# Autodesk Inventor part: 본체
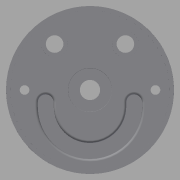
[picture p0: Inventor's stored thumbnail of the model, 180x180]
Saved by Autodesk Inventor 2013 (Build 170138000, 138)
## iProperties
Created: 2015-04
Part Number: 본체
Material: 일반
Document SubType Name: Modeling
Designer: WINDOWS7
Density: 1 g/cm^3
Author: WINDOWS7
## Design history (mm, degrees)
sketch "스케치1"
  geometry: C1 r 95 at (0, 0); 1 further point
  constraints: 1 centre point, 1 coincident
  dimensions: "d0" = 190 diameter of C1
extrude "돌출1" new body sketch "스케치1" distance "d1" = 32; taper "d2" = 0 deg
sketch "스케치2"
  geometry: L1 (0, 0)-(95, 0); L2 (0, 0)-(94.638, -8.28); L3 (0, 0)-(0, -95); L4 (0, 0)-(-94.638, -8.28); A1 r 95 centre (0, 0) between (95, 0) and (0, -95) reference; A2 r 95 centre (0, 0) between (-94.638, -8.28) and (94.638, -8.28)
  constraints: 8 end point, 6 point on circle, 1 centre point, 1 coincident, 1 horizontal, 1 perpendicular, 1 symmetric about line
  dimensions: "d3" = 5 deg angle of L1 L2
extrude "돌출2" cut sketch "스케치2" distance "d4" = 5; taper "d5" = 0 deg
sketch "스케치3"
  geometry: L1 (0, 0)-(-95, 0); L2 (0, 0)-(-50.912, 50.912); L3 (0, 0)-(0, 95); L4 (0, 0)-(50.912, 50.912); L5 (36.062, 36.062)-(50.912, 50.912); L6 (-36.062, 36.062)-(-50.912, 50.912); A1 r 95 centre (0, 0) between (-95, 0) and (0, 95) reference; A2 r 51 centre (0, 0) between (36.062, 36.062) and (-36.062, 36.062); A3 r 72 centre (0, 0) between (50.912, 50.912) and (-50.912, 50.912)
  constraints: 12 end point, 6 point on circle, 2 centre point, 2 coincident, 2 point on line, 1 collinear, 1 horizontal, 1 perpendicular, 1 symmetric about line
  dimensions: "d8" = 51 radius of A2; "d10" = 72 radius of A3; "d11" = 90 deg angle of L2 L4
extrude "돌출3" join sketch "스케치3" distance "d12" = 5.5; taper "d13" = 0 deg
fillet "모깎기1" dims "d14" = 5
sketch "스케치4"
  geometry: L1 (0, 0)-(100.649, 0); L2 (-89.196, 12)-(-40.249, 12); L3 (40.249, 12)-(89.196, 12); A1 r 95 centre (0, 0) between (94.638, -8.28) and (-94.638, -8.28) reference; A2 r 42 centre (0, 0) between (40.249, 12) and (-40.249, 12); A3 r 90 centre (0, 0) between (89.196, 12) and (-89.196, 12)
  constraints: 6 end point, 4 point on circle, 2 centre point, 2 coincident, 2 parallel, 1 horizontal
  dimensions: "d50" = 12 distance between parallel lines of L3 L1; "d52" = 42 radius of A2; "d54" = 90 radius of A3; "d55" = 12 distance between parallel lines of L1 L2
extrude "돌출9" cut sketch "스케치4" distance "d56" = 25; taper "d57" = 0 deg
fillet "모깎기2" dims "d58" = 10
sketch "스케치7"
  geometry: L1 (-47.117, 12)-(-76.916, 12) reference; L2 (76.916, 12)-(47.117, 12) reference; C1 r 90 at (0, 0); A1 r 42 centre (0, 0) between (38.056, 17.769) and (-38.056, 17.769) reference; A2 r 10 centre (-47.117, 22) between (-47.117, 12) and (-38.056, 17.769) reference; A3 r 10 centre (-76.916, 22) between (-86.53, 24.75) and (-76.916, 12) reference; A4 r 90 centre (0, 0) between (86.53, 24.75) and (-86.53, 24.75) reference; A5 r 10 centre (76.916, 22) between (76.916, 12) and (86.53, 24.75) reference; A6 r 10 centre (47.117, 22) between (38.056, 17.769) and (47.117, 12) reference; A7 r 95 centre (0, 0) between (94.638, -8.28) and (-94.638, -8.28) reference
  constraints: 1 centre point, 1 coincident
  dimensions: "d59" = 180 diameter of C1
extrude "돌출10" cut sketch "스케치7" distance "d61" = 18; taper "d62" = 0 deg
sketch "스케치8"
  geometry: L1 (47.117, 12)-(76.916, 12) reference; L2 (-76.916, 12)-(-47.117, 12) reference; L3 (0, 0)-(0, -49.147); L4 (0, 0)-(49.869, 0); L5 (-59, -19)-(-41, -19); L6 (41, -19)-(59, -19); L7 (-59, -14)-(-41, -14); L8 (-59, -19)-(-59, -14); L9 (-41, -19)-(-41, -14); L10 (41, -19)-(41, -14); L11 (59, -19)-(59, -14); L12 (59, -14)-(41, -14); A1 r 42 centre (0, 0) between (38.056, 17.769) and (-38.056, 17.769) reference; A2 r 59 centre (0, -19) between (-59, -19) and (59, -19); A3 r 41 centre (0, -19) between (-41, -19) and (41, -19); A4 r 9 centre (-50, -14) between (-41, -14) and (-59, -14); A5 r 9 centre (50, -14) between (59, -14) and (41, -14)
  constraints: 20 end point, 8 point on circle, 7 parallel, 4 centre point, 3 perpendicular, 3 symmetric about line, 2 coincident, 2 tangent, 1 midpoint, 1 point on line, 1 other
  dimensions: "d75" = 118 diameter of A2; "d76" = 82 diameter of A3; "d79" = 19 distance between parallel lines of L4 L6; "d116" = 5 distance between parallel lines of L6 L12
extrude "돌출11" cut sketch "스케치8" distance "d81" = 7; taper "d82" = 0 deg
sketch "스케치9"
  geometry: C1 r 95 at (0, 0) reference; C2 r 11.5 at (0, 0)
  constraints: 1 centre point, 1 coincident
  dimensions: "d83" = 23 diameter of C2
extrude "돌출12" cut sketch "스케치9" stored distance "d85" = 7; taper "d86" = 0 deg
sketch "스케치10"
  geometry: C1 r 25 at (0, 0); A1 r 95 centre (0, 0) between (94.638, -8.28) and (-94.638, -8.28) reference
  constraints: 1 centre point, 1 coincident
  dimensions: "d87" = 50 diameter of C1
extrude "돌출13" cut sketch "스케치10" distance "d89" = 25; taper "d90" = 0 deg
fillet "모깎기3" dims "d91" = 1
fillet "모깎기4" dims "d92" = 0.3
sketch "스케치11"
  geometry: L1 (0, 0)-(0, 90); C1 r 10 at (-40, 52); C2 r 15 at (-40, 52); C3 r 15 at (40, 52); C4 r 10 at (40, 52); A1 r 90 centre (0, 0) between (86.53, 24.75) and (-86.53, 24.75) reference; A2 r 42 centre (0, 0) between (38.056, 17.769) and (-38.056, 17.769) reference
  constraints: 4 centre point, 2 coincident, 2 end point, 2 symmetric about line, 1 point on circle, 2 other
  dimensions: "d93" = 80 distance of C3.centre C1.centre; "d95" = 20 diameter of C4; "d96" = 30 diameter of C3; "d97" = 52 vertical distance of C1.centre A1.centre
extrude "돌출14" join sketch "스케치11" distance "d98" = 25; taper "d99" = 0 deg
sketch "스케치12"
  geometry: L1 (-49.658, -59.844)-(-54.638, -60.28) reference; L2 (134.638, -60.28)-(129.658, -59.844) reference; L3 (0, 0)-(0, 19.2); L4 (-6, 13.748)-(-6, -13.748); L5 (6, 13.748)-(6, -13.748); C1 r 10 at (0, 0) reference; C2 r 10 at (80, 0) reference; C3 r 15 at (80, 0) reference; A1 r 15 centre (0, 0) between (6, 13.748) and (-6, 13.748) reference; A2 r 95 centre (40, -52) between (134.638, -60.28) and (-54.638, -60.28) reference; A3 r 90 centre (40, -52) between (129.658, -59.844) and (-49.658, -59.844) reference; 1 further point
  constraints: 6 end point, 4 point on circle, 1 parallel, 1 vertical
  dimensions: "d100" = 12 distance between parallel lines of L4 L5
extrude "돌출15" cut sketch "스케치12" distance "d102" = 3; taper "d103" = 0 deg
fillet "모깎기5" dims "d104" = 3
sketch "스케치13"
  geometry: L1 (99, -71)-(99, -66) reference; L2 (81, -66)-(81, -71) reference; L3 (-1, -71)-(-1, -66) reference; L4 (-19, -66)-(-19, -71) reference; L5 (87.117, -40)-(116.916, -40) reference; L6 (-36.916, -40)-(-7.117, -40) reference; C1 r 10 at (0, 0) reference; C2 r 15 at (80, 0) reference; C3 r 10 at (0, 0) reference; C4 r 15 at (0, 0) reference; C5 r 10 at (80, 0) reference; C6 r 24.7 at (40, -52) reference; C7 r 11.5 at (40, -52) reference; C8 r 95 at (40, -52) reference; A1 r 9 centre (90, -66) between (99, -66) and (81, -66) reference; A2 r 41 centre (40, -71) between (-1, -71) and (81, -71) reference; A3 r 9 centre (-10, -66) between (-1, -66) and (-19, -66) reference; A4 r 59 centre (40, -71) between (-19, -71) and (99, -71) reference; A5 r 10 centre (87.117, -30) between (78.056, -34.231) and (87.117, -40) reference; A6 r 10 centre (116.916, -30) between (116.916, -40) and (126.53, -27.25) reference; A7 r 90 centre (40, -52) between (126.53, -27.25) and (-46.53, -27.25) reference; A8 r 10 centre (-36.916, -30) between (-46.53, -27.25) and (-36.916, -40) reference; A9 r 10 centre (-7.117, -30) between (-7.117, -40) and (1.944, -34.231) reference; A10 r 42 centre (40, -52) between (78.056, -34.231) and (1.944, -34.231) reference; 1 further point
extrude "돌출16" cut sketch "스케치13" stored distance "d105" = 3; taper "d106" = 0 deg
sketch "스케치14"
  geometry: L1 (0, 0)-(-95, 0); L2 (0, 0)-(0, -95); A1 r 95 centre (0, 0) between (-95, 0) and (0, -95) reference; A2 r 75 centre (0, 0) between (48.927, 56.843) and (-48.927, 56.843) reference; 2 further points
  constraints: 4 end point, 2 point on circle, 1 horizontal, 1 perpendicular, 1 point on line, 1 symmetric about line
  dimensions: "d107" = 148 distance of point (-74, 0) point (74, 0)
hole "구멍1" sketch "스케치14" at (-74, 0), (74, 0) diameter "d109" = 11; stored, may be unused: countersink angle "d113" = 90 deg, drill point angle "d115" = 118 deg; dims "d110" = 6, "d111" = 18, "d112" = 11, "d114" = 8
fillet "모깎기6" dims "d117" = 5
fillet "모깎기7" dims "d118" = 3
node "솔리드1"
mirror "대칭1"
node "절단 모서리 투영1"
node "절단 모서리 투영2"
other parameters: "d36" = 84, "d48" = 84, "d49" = 12, "d65" = 19, "d77" = 12
